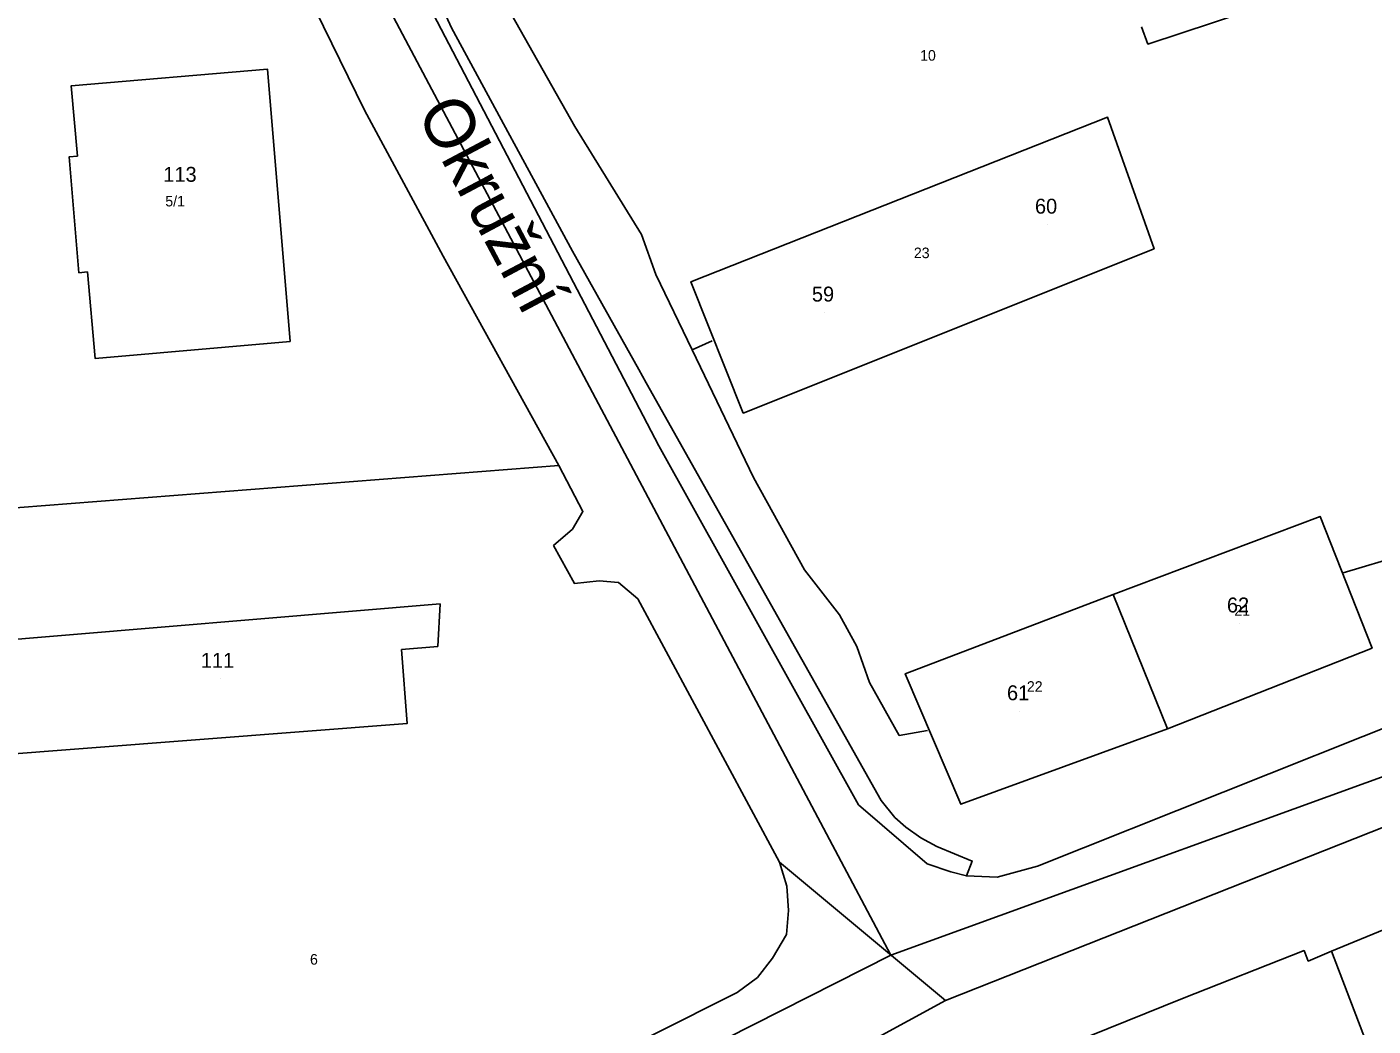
# Model space of a CAD drawing. Extents: x -873642 to -872917, y -1012962 to -1012567.
# Drawn here: x -873481.3 to -873373.1, y -1012828.2 to -1012747.9 of the extents above; entities that cross this region are included whole.
import ezdxf

# ---------------------------------------------------------------- set-up
doc = ezdxf.new("R2010")
doc.units = 0
for name, color, linetype in [('adresni_misto', 7, 'Continuous'), ('cisla_parcelni_kn', 7, 'Continuous'), ('cislo_domovni', 7, 'Continuous'), ('osy_ulic', 7, 'Continuous'), ('parcely_kn', 7, 'Continuous'), ('stavebni_objekty_bydleni', 7, 'Continuous'), ('TRASY - zamereno', 7, 'Continuous'), ('ulice', 7, 'Continuous')]:
    doc.layers.add(name, color=color, linetype=linetype)

msp = doc.modelspace()

# ---------------------------------------------------------------- linework, layer by layer
at = {"layer": 'adresni_misto'}
for p, q in [((-873468.76, -1012761.25), (-873468.76, -1012761.25)), ((-873399.25, -1012763.81), (-873399.25, -1012763.81)), ((-873417.19, -1012770.88), (-873417.19, -1012770.88)), ((-873383.81, -1012795.88), (-873383.81, -1012795.88)), ((-873465.74, -1012800.33), (-873465.74, -1012800.33)), ((-873401.5, -1012802.94), (-873401.5, -1012802.94))]:
    msp.add_line(p, q, dxfattribs=at)
at = {"layer": 'osy_ulic'}
for points in [[(-873411.85, -1012822.53), (-873317.85, -1012788.44), (-873277.23, -1012773.91), (-873252.76, -1012767.01), (-873201.18, -1012755.57), (-873115.6, -1012739.3), (-873104.65, -1012731.3), (-873088.93, -1012706.26), (-873080.41, -1012681.66), (-873071.61, -1012653.78), (-873070.57, -1012650.45), (-873066.08, -1012632.13), (-873063.74, -1012625.63), (-873059.56, -1012597.3)], [(-873471.18, -1012707.47), (-873461.48, -1012728.93), (-873411.85, -1012822.53)], [(-873411.85, -1012822.53), (-873495.73, -1012864.97), (-873510.64, -1012868.38), (-873524.3, -1012868.21), (-873541.44, -1012862.33)]]:
    msp.add_lwpolyline(points, dxfattribs=at)
at = {"layer": 'parcely_kn'}
for points in [[(-873492.26, -1012636.3), (-873470.15, -1012634.51), (-873474.09, -1012635.88), (-873476.25, -1012638.16), (-873476.91, -1012642.49), (-873474.55, -1012659.21), (-873473.95, -1012664.84), (-873471.34, -1012679.34), (-873470.31, -1012685.53), (-873467.35, -1012700.29), (-873461.39, -1012719.27), (-873456.13, -1012732.5), (-873430.5, -1012781.58), (-873414.44, -1012810.45), (-873408.91, -1012815.19), (-873407.03, -1012815.83), (-873405.77, -1012816.17), (-873403.3, -1012816.28), (-873400.05, -1012815.37), (-873370.19, -1012803.49), (-873353.25, -1012796.68), (-873342.17, -1012792.27), (-873320.46, -1012784.28)], [(-873492.26, -1012636.3), (-873470.15, -1012634.51), (-873474.09, -1012635.88), (-873476.25, -1012638.16), (-873476.91, -1012642.49), (-873474.55, -1012659.21), (-873473.95, -1012664.84), (-873471.34, -1012679.34), (-873470.31, -1012685.53), (-873467.35, -1012700.29), (-873461.39, -1012719.27), (-873456.13, -1012732.5), (-873430.5, -1012781.58), (-873414.44, -1012810.45), (-873408.91, -1012815.19), (-873407.03, -1012815.83), (-873405.77, -1012816.17), (-873403.3, -1012816.28), (-873400.05, -1012815.37), (-873370.19, -1012803.49), (-873353.25, -1012796.68), (-873342.17, -1012792.27), (-873320.46, -1012784.28)], [(-873267.15, -1012775.08), (-873296.21, -1012784.7), (-873317.65, -1012791.79), (-873327.22, -1012794.59), (-873352.28, -1012804.24), (-873370.67, -1012811.62), (-873407.44, -1012826.19), (-873420.81, -1012815.05), (-873432.2, -1012793.89), (-873433.76, -1012792.56), (-873435.3, -1012792.45), (-873437.28, -1012792.66), (-873438.97, -1012789.6), (-873437.44, -1012788.27), (-873436.61, -1012786.86), (-873438.55, -1012783.17), (-873447.85, -1012766.32), (-873454.18, -1012754.58), (-873460.09, -1012742.48), (-873462.37, -1012737.41), (-873469.44, -1012722.44), (-873475.56, -1012699.33), (-873477.8, -1012685.05)], [(-873267.15, -1012775.08), (-873296.21, -1012784.7), (-873317.65, -1012791.79), (-873327.22, -1012794.59), (-873352.28, -1012804.24), (-873370.67, -1012811.62), (-873407.44, -1012826.19), (-873420.81, -1012815.05), (-873432.2, -1012793.89), (-873433.76, -1012792.56), (-873435.3, -1012792.45), (-873437.28, -1012792.66), (-873438.97, -1012789.6), (-873437.44, -1012788.27), (-873436.61, -1012786.86), (-873438.55, -1012783.17), (-873447.85, -1012766.32), (-873454.18, -1012754.58), (-873460.09, -1012742.48), (-873462.37, -1012737.41), (-873469.44, -1012722.44), (-873475.56, -1012699.33), (-873477.8, -1012685.05)], [(-873469.44, -1012722.44), (-873462.37, -1012737.41), (-873460.09, -1012742.48), (-873454.18, -1012754.58), (-873447.85, -1012766.32), (-873438.55, -1012783.17), (-873498.44, -1012787.82), (-873499.25, -1012788.65), (-873498.73, -1012794.57), (-873498.47, -1012798.05), (-873510.35, -1012799.3), (-873495.72, -1012765.36), (-873494.38, -1012762.24), (-873490.76, -1012753.79), (-873478.18, -1012725.33)], [(-873469.44, -1012722.44), (-873462.37, -1012737.41), (-873460.09, -1012742.48), (-873454.18, -1012754.58), (-873447.85, -1012766.32), (-873438.55, -1012783.17), (-873498.44, -1012787.82), (-873499.25, -1012788.65), (-873498.73, -1012794.57), (-873498.47, -1012798.05), (-873510.35, -1012799.3), (-873495.72, -1012765.36), (-873494.38, -1012762.24), (-873490.76, -1012753.79), (-873478.18, -1012725.33)], [(-873454.45, -1012732.08), (-873447.17, -1012747.96), (-873437.44, -1012765.92), (-873432.12, -1012775.44), (-873431.53, -1012776.51), (-873412.61, -1012810.11), (-873411.51, -1012811.47), (-873410.65, -1012812.25), (-873409.43, -1012813.1), (-873408.13, -1012813.8), (-873405.3, -1012814.98), (-873405.77, -1012816.17), (-873407.03, -1012815.83), (-873408.91, -1012815.19), (-873414.44, -1012810.45), (-873430.5, -1012781.58), (-873456.13, -1012732.5)], [(-873454.45, -1012732.08), (-873447.17, -1012747.96), (-873437.44, -1012765.92), (-873432.12, -1012775.44), (-873431.53, -1012776.51), (-873412.61, -1012810.11), (-873411.51, -1012811.47), (-873410.65, -1012812.25), (-873409.43, -1012813.1), (-873408.13, -1012813.8), (-873405.3, -1012814.98), (-873405.77, -1012816.17), (-873407.03, -1012815.83), (-873408.91, -1012815.19), (-873414.44, -1012810.45), (-873430.5, -1012781.58), (-873456.13, -1012732.5)], [(-873370.19, -1012803.49), (-873400.05, -1012815.37), (-873403.3, -1012816.28), (-873405.77, -1012816.17), (-873405.3, -1012814.98), (-873408.13, -1012813.8), (-873409.43, -1012813.1), (-873410.65, -1012812.25), (-873411.51, -1012811.47), (-873412.61, -1012810.11), (-873431.53, -1012776.51), (-873432.12, -1012775.44), (-873437.44, -1012765.92), (-873447.17, -1012747.96), (-873454.45, -1012732.08)], [(-873370.19, -1012803.49), (-873400.05, -1012815.37), (-873403.3, -1012816.28), (-873405.77, -1012816.17), (-873405.3, -1012814.98), (-873408.13, -1012813.8), (-873409.43, -1012813.1), (-873410.65, -1012812.25), (-873411.51, -1012811.47), (-873412.61, -1012810.11), (-873431.53, -1012776.51), (-873432.12, -1012775.44), (-873437.44, -1012765.92), (-873447.17, -1012747.96), (-873454.45, -1012732.08)], [(-873391.67, -1012747.88), (-873391.16, -1012749.27), (-873372.72, -1012743.18)], [(-873372.72, -1012743.18), (-873391.16, -1012749.27), (-873391.67, -1012747.88)], [(-873391.67, -1012747.88), (-873391.16, -1012749.27), (-873372.72, -1012743.18)], [(-873372.72, -1012743.18), (-873391.16, -1012749.27), (-873391.67, -1012747.88)], [(-873491.56, -1012871.97), (-873407.44, -1012826.19), (-873370.67, -1012811.62), (-873352.28, -1012804.24), (-873327.22, -1012794.59), (-873317.65, -1012791.79), (-873296.21, -1012784.7), (-873295.08, -1012789.07), (-873304.48, -1012791.83), (-873302.28, -1012798.85), (-873296.89, -1012797.13), (-873293, -1012795.88), (-873288.89, -1012809.97), (-873206.66, -1012788.54), (-873209.55, -1012779.29), (-873212.49, -1012767.05), (-873213.62, -1012762.14), (-873185.58, -1012756.25), (-873148.18, -1012749.22)], [(-873491.56, -1012871.97), (-873407.44, -1012826.19), (-873370.67, -1012811.62), (-873352.28, -1012804.24), (-873327.22, -1012794.59), (-873317.65, -1012791.79), (-873296.21, -1012784.7), (-873295.08, -1012789.07), (-873304.48, -1012791.83), (-873302.28, -1012798.85), (-873296.89, -1012797.13), (-873293, -1012795.88), (-873288.89, -1012809.97), (-873206.66, -1012788.54), (-873209.55, -1012779.29), (-873212.49, -1012767.05), (-873213.62, -1012762.14), (-873185.58, -1012756.25), (-873148.18, -1012749.22)], [(-873498.44, -1012787.82), (-873438.55, -1012783.17), (-873436.61, -1012786.86), (-873437.44, -1012788.27), (-873438.97, -1012789.6), (-873437.28, -1012792.66), (-873435.3, -1012792.45), (-873433.76, -1012792.56), (-873432.2, -1012793.89), (-873420.81, -1012815.05), (-873420.2, -1012816.99), (-873420.07, -1012818.95), (-873420.24, -1012820.89), (-873421.37, -1012822.77), (-873422.58, -1012824.33), (-873424.19, -1012825.53), (-873491.75, -1012859.41)], [(-873498.44, -1012787.82), (-873438.55, -1012783.17), (-873436.61, -1012786.86), (-873437.44, -1012788.27), (-873438.97, -1012789.6), (-873437.28, -1012792.66), (-873435.3, -1012792.45), (-873433.76, -1012792.56), (-873432.2, -1012793.89), (-873420.81, -1012815.05), (-873420.2, -1012816.99), (-873420.07, -1012818.95), (-873420.24, -1012820.89), (-873421.37, -1012822.77), (-873422.58, -1012824.33), (-873424.19, -1012825.53), (-873491.75, -1012859.41)]]:
    msp.add_lwpolyline(points, dxfattribs=at)
for points in [[(-873477.27, -1012758.28), (-873477.77, -1012752.62), (-873461.99, -1012751.28), (-873460.16, -1012773.18), (-873475.85, -1012774.55), (-873476.46, -1012767.59), (-873477.15, -1012767.66), (-873477.92, -1012758.34)], [(-873477.15, -1012767.66), (-873476.46, -1012767.59), (-873475.85, -1012774.55), (-873460.16, -1012773.18), (-873461.99, -1012751.28), (-873477.77, -1012752.62), (-873477.27, -1012758.28), (-873477.92, -1012758.34)], [(-873477.27, -1012758.28), (-873477.77, -1012752.62), (-873461.99, -1012751.28), (-873460.16, -1012773.18), (-873475.85, -1012774.55), (-873476.46, -1012767.59), (-873477.15, -1012767.66), (-873477.92, -1012758.34)], [(-873477.15, -1012767.66), (-873476.46, -1012767.59), (-873475.85, -1012774.55), (-873460.16, -1012773.18), (-873461.99, -1012751.28), (-873477.77, -1012752.62), (-873477.27, -1012758.28), (-873477.92, -1012758.34)], [(-873423.71, -1012778.95), (-873390.67, -1012765.73), (-873394.41, -1012755.16), (-873427.92, -1012768.39)], [(-873390.67, -1012765.73), (-873423.71, -1012778.95), (-873427.92, -1012768.39), (-873394.41, -1012755.16)], [(-873423.71, -1012778.95), (-873390.67, -1012765.73), (-873394.41, -1012755.16), (-873427.92, -1012768.39)], [(-873390.67, -1012765.73), (-873423.71, -1012778.95), (-873427.92, -1012768.39), (-873394.41, -1012755.16)], [(-873389.58, -1012804.35), (-873373.13, -1012797.84), (-873377.32, -1012787.26), (-873393.96, -1012793.53), (-873410.68, -1012799.91), (-873406.22, -1012810.4)], [(-873389.58, -1012804.35), (-873373.13, -1012797.84), (-873377.32, -1012787.26), (-873393.96, -1012793.53), (-873410.68, -1012799.91), (-873406.22, -1012810.4)], [(-873377.32, -1012787.26), (-873373.13, -1012797.84), (-873389.58, -1012804.35), (-873393.96, -1012793.53)], [(-873377.32, -1012787.26), (-873373.13, -1012797.84), (-873389.58, -1012804.35), (-873393.96, -1012793.53)], [(-873410.68, -1012799.91), (-873393.96, -1012793.53), (-873389.58, -1012804.35), (-873406.22, -1012810.4)], [(-873410.68, -1012799.91), (-873393.96, -1012793.53), (-873389.58, -1012804.35), (-873406.22, -1012810.4)], [(-873379.34, -1012875.83), (-873373.58, -1012889.78), (-873355.03, -1012878.22), (-873289.09, -1012837.11), (-873306.1, -1012794.62), (-873364.45, -1012817.23), (-873371.7, -1012820.28), (-873376.39, -1012822.23), (-873378.27, -1012823.02), (-873378.61, -1012822.17), (-873388.38, -1012826.03), (-873398.8, -1012830.22), (-873398.3, -1012831.4), (-873382.99, -1012867.41)], [(-873379.34, -1012875.83), (-873373.58, -1012889.78), (-873355.03, -1012878.22), (-873289.09, -1012837.11), (-873306.1, -1012794.62), (-873364.45, -1012817.23), (-873371.7, -1012820.28), (-873376.39, -1012822.23), (-873378.27, -1012823.02), (-873378.61, -1012822.17), (-873388.38, -1012826.03), (-873398.8, -1012830.22), (-873398.3, -1012831.4), (-873382.99, -1012867.41)], [(-873364.45, -1012817.23), (-873306.1, -1012794.62), (-873289.09, -1012837.11), (-873355.03, -1012878.22), (-873364.42, -1012853.62), (-873375.46, -1012858.04), (-873381.76, -1012842.3), (-873370.46, -1012837.78), (-873376.39, -1012822.23), (-873371.7, -1012820.28)], [(-873364.45, -1012817.23), (-873306.1, -1012794.62), (-873289.09, -1012837.11), (-873355.03, -1012878.22), (-873364.42, -1012853.62), (-873375.46, -1012858.04), (-873381.76, -1012842.3), (-873370.46, -1012837.78), (-873376.39, -1012822.23), (-873371.7, -1012820.28)], [(-873407.44, -1012826.19), (-873491.56, -1012871.97), (-873510.35, -1012874.83), (-873513.75, -1012874.06), (-873521.64, -1012872.77), (-873517.87, -1012866.9), (-873506.6, -1012864.53), (-873501.14, -1012863.39), (-873495.55, -1012861.22), (-873491.75, -1012859.41), (-873424.19, -1012825.53), (-873422.58, -1012824.33), (-873421.37, -1012822.77), (-873420.24, -1012820.89), (-873420.07, -1012818.95), (-873420.2, -1012816.99), (-873420.81, -1012815.05)], [(-873407.44, -1012826.19), (-873491.56, -1012871.97), (-873510.35, -1012874.83), (-873513.75, -1012874.06), (-873521.64, -1012872.77), (-873517.87, -1012866.9), (-873506.6, -1012864.53), (-873501.14, -1012863.39), (-873495.55, -1012861.22), (-873491.75, -1012859.41), (-873424.19, -1012825.53), (-873422.58, -1012824.33), (-873421.37, -1012822.77), (-873420.24, -1012820.89), (-873420.07, -1012818.95), (-873420.2, -1012816.99), (-873420.81, -1012815.05)], [(-873355.03, -1012878.22), (-873373.58, -1012889.78), (-873379.34, -1012875.83), (-873382.99, -1012867.41), (-873398.3, -1012831.4), (-873398.8, -1012830.22), (-873388.38, -1012826.03), (-873378.61, -1012822.17), (-873378.27, -1012823.02), (-873376.39, -1012822.23), (-873370.46, -1012837.78), (-873381.76, -1012842.3), (-873375.46, -1012858.04), (-873364.42, -1012853.62)], [(-873355.03, -1012878.22), (-873373.58, -1012889.78), (-873379.34, -1012875.83), (-873382.99, -1012867.41), (-873398.3, -1012831.4), (-873398.8, -1012830.22), (-873388.38, -1012826.03), (-873378.61, -1012822.17), (-873378.27, -1012823.02), (-873376.39, -1012822.23), (-873370.46, -1012837.78), (-873381.76, -1012842.3), (-873375.46, -1012858.04), (-873364.42, -1012853.62)]]:
    msp.add_lwpolyline(points, close=True, dxfattribs=at)
at = {"layer": 'stavebni_objekty_bydleni'}
for points in [[(-873477.15, -1012767.66), (-873477.92, -1012758.34), (-873477.27, -1012758.28), (-873477.77, -1012752.62), (-873461.99, -1012751.28), (-873460.16, -1012773.18), (-873475.85, -1012774.55), (-873476.46, -1012767.59)], [(-873390.67, -1012765.73), (-873423.71, -1012778.95), (-873427.92, -1012768.39), (-873394.41, -1012755.16)], [(-873389.58, -1012804.35), (-873406.22, -1012810.4), (-873410.68, -1012799.91), (-873393.96, -1012793.53), (-873377.32, -1012787.26), (-873373.13, -1012797.84)], [(-873448.09, -1012794.28), (-873448.28, -1012797.71), (-873451.2, -1012797.96), (-873450.74, -1012803.9), (-873484.83, -1012806.53), (-873485.3, -1012797.4)]]:
    msp.add_lwpolyline(points, close=True, dxfattribs=at)
at = {"layer": 'TRASY - zamereno'}
for p, q in [((-873443.35, -1012745.12), (-873437.27, -1012755.9)), ((-873437.27, -1012755.9), (-873431.89, -1012764.6)), ((-873431.89, -1012764.6), (-873430.74, -1012767.8)), ((-873430.74, -1012767.8), (-873427.81, -1012773.87)), ((-873427.81, -1012773.87), (-873426.21, -1012773.14)), ((-873427.81, -1012773.87), (-873422.88, -1012784.13)), ((-873422.88, -1012784.13), (-873418.78, -1012791.54)), ((-873375.47, -1012791.79), (-873370.51, -1012790.31)), ((-873418.78, -1012791.54), (-873415.97, -1012795.18)), ((-873415.97, -1012795.18), (-873414.58, -1012797.72)), ((-873414.58, -1012797.72), (-873413.56, -1012800.62)), ((-873413.56, -1012800.62), (-873411.18, -1012804.88)), ((-873411.18, -1012804.88), (-873408.9, -1012804.47))]:
    msp.add_line(p, q, dxfattribs=at)

# ---------------------------------------------------------------- texts
at = {"layer": 'cisla_parcelni_kn'}
for s, p in [('10', (-873409.49, -1012750.61)), ('10', (-873409.49, -1012750.61)), ('5/1', (-873470.2, -1012762.33)), ('5/1', (-873470.2, -1012762.33)), ('23', (-873409.99, -1012766.49)), ('23', (-873409.99, -1012766.49)), ('21', (-873384.21, -1012795.24)), ('21', (-873384.21, -1012795.24)), ('22', (-873400.9, -1012801.36)), ('22', (-873400.9, -1012801.36)), ('6', (-873458.56, -1012823.3)), ('6', (-873458.56, -1012823.3))]:
    msp.add_text(s, height=0.85, dxfattribs=at).set_placement(p)
at = {"layer": 'cislo_domovni'}
for s, p in [('113', (-873470.36, -1012760.35)), ('60', (-873400.25, -1012762.91)), ('59', (-873418.19, -1012769.98)), ('62', (-873384.81, -1012794.98)), ('111', (-873467.34, -1012799.43)), ('61', (-873402.5, -1012802.04))]:
    msp.add_text(s, height=1.2, dxfattribs=at).set_placement(p)
at = {"layer": 'ulice'}
msp.add_text('Okružní', height=4, rotation=297.9341, dxfattribs=at).set_placement((-873450.04, -1012754.77))

doc.saveas('drawing.dxf')
